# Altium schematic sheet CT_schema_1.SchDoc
size 464 x 450 mm
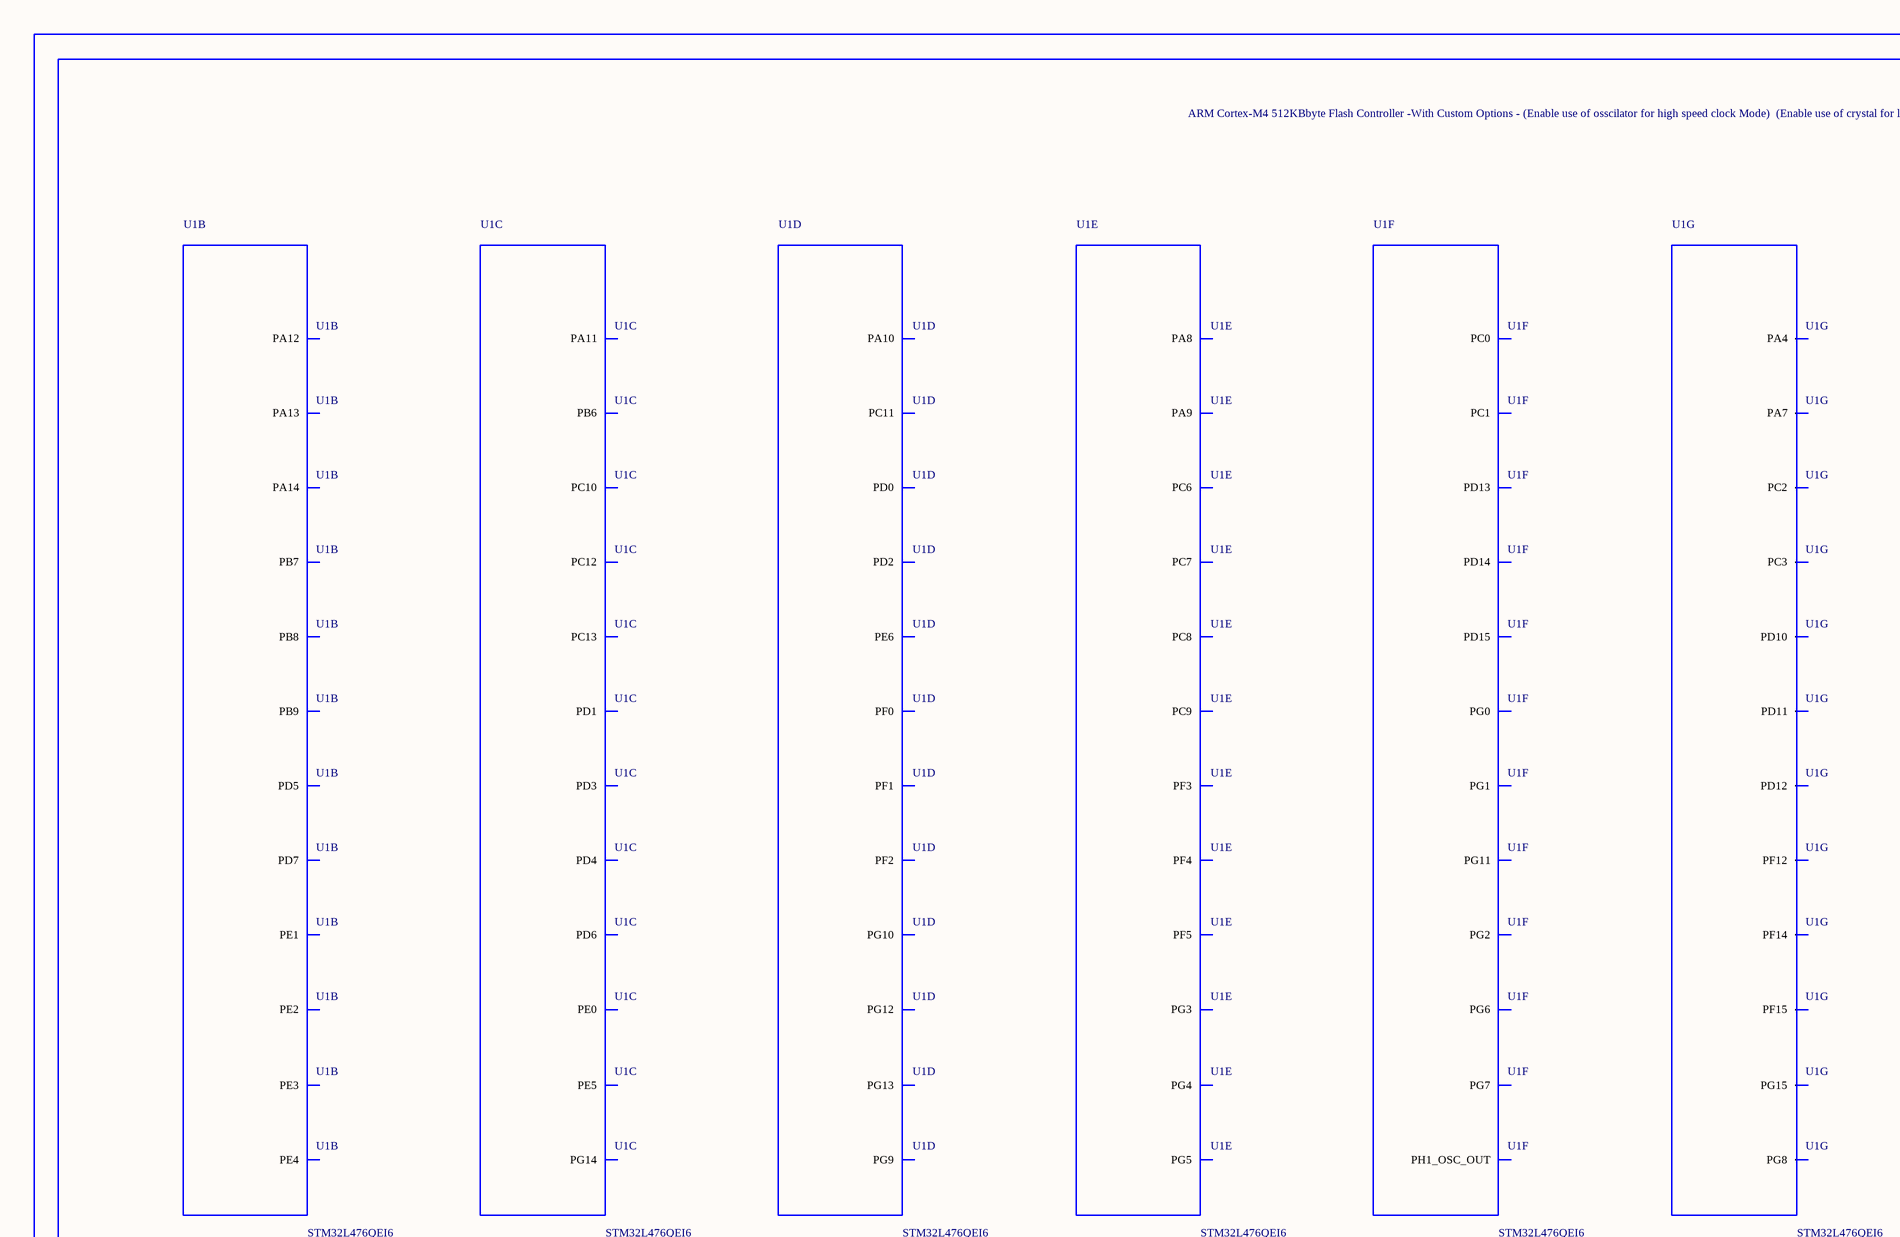
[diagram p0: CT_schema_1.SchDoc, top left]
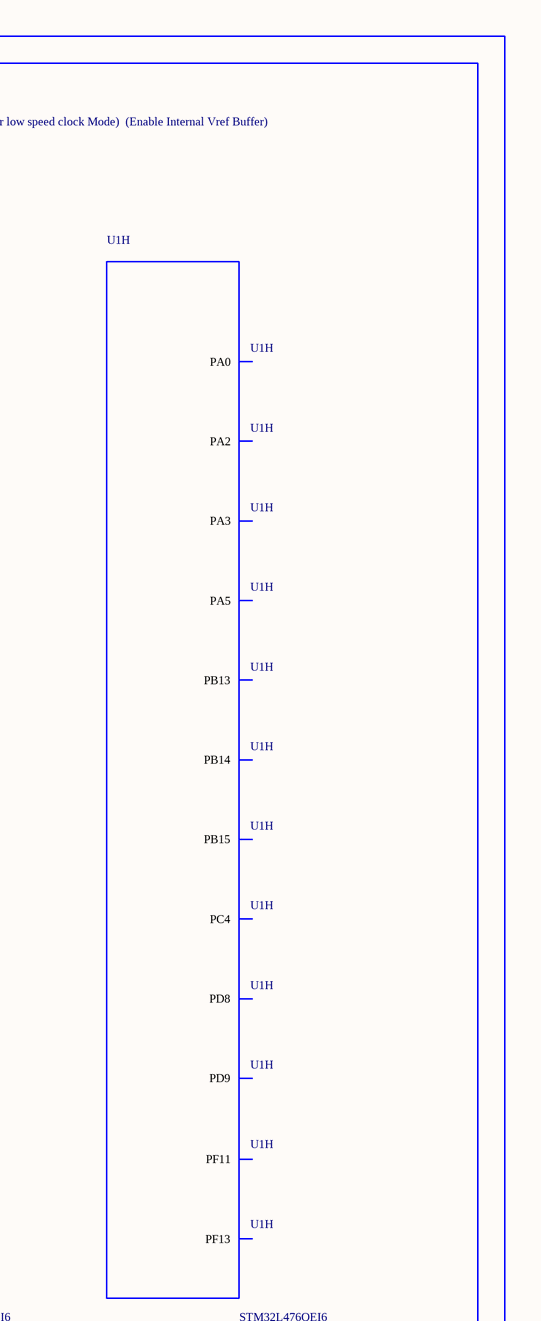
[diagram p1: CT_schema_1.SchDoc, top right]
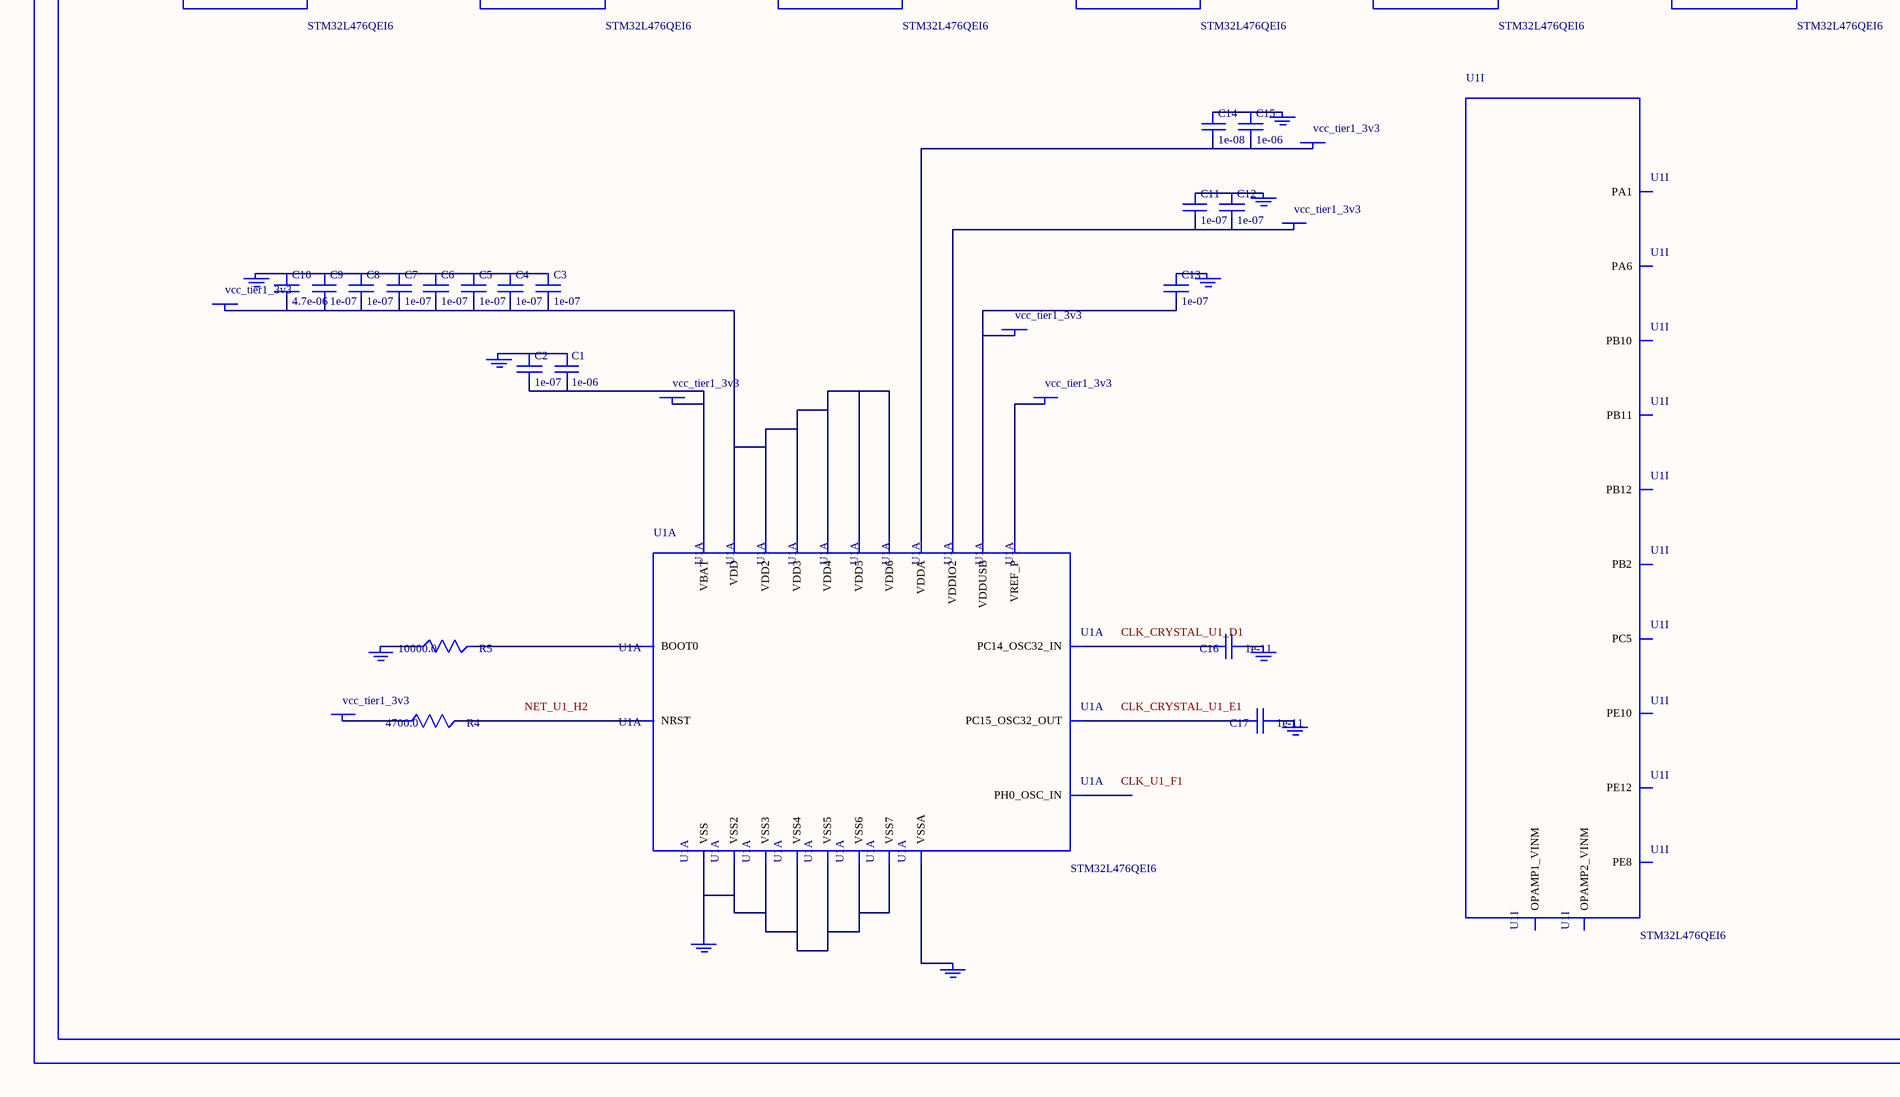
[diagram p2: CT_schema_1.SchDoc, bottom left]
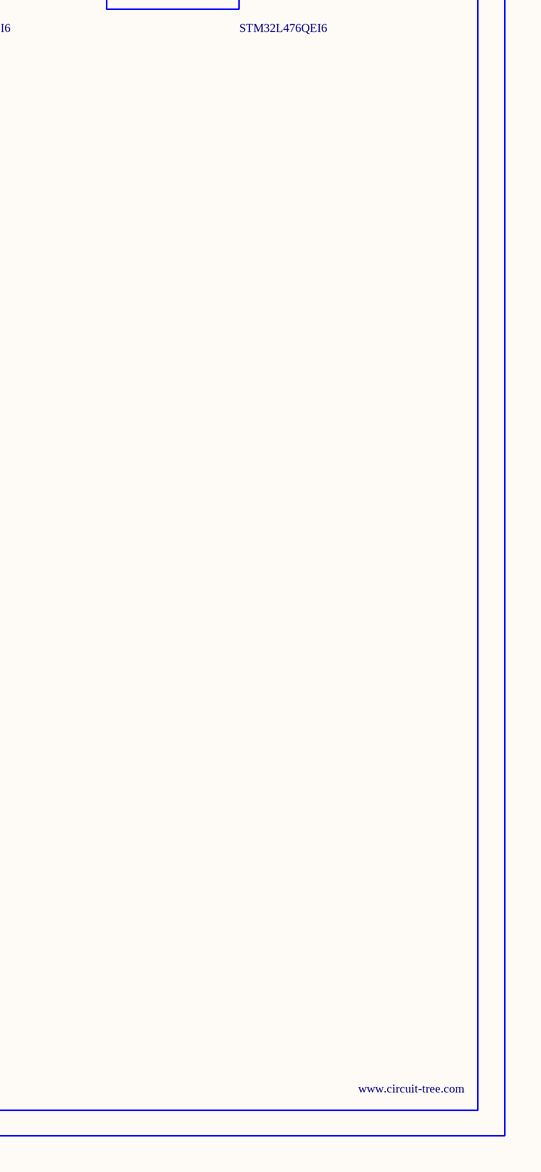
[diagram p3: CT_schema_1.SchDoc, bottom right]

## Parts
BORDER0  (no value)
C1  1e-06  [C0603]
C2  1e-07  [C0603]
C3  1e-07  [C0603]
C4  1e-07  [C0603]
C5  1e-07  [C0603]
C6  1e-07  [C0603]
C7  1e-07  [C0603]
C8  1e-07  [C0603]
C9  1e-07  [C0603]
C10  4.7e-06  [C0603]
C11  1e-07  [C0603]
C12  1e-07  [C0603]
C13  1e-07  [C0603]
C14  1e-08  [C0603]
C15  1e-06  [C0603]
C16  1e-11  [C0402]
C17  1e-11  [C0402]
GND_INSTANCE_0_0  (no value)
GND_INSTANCE_0_1  (no value)
GND_INSTANCE_0_2  (no value)
GND_INSTANCE_0_3  (no value)
GND_INSTANCE_0_4  (no value)
GND_INSTANCE_0_5  (no value)
GND_INSTANCE_0_6  (no value)
GND_INSTANCE_0_7  (no value)
GND_INSTANCE_0_8  (no value)
GND_INSTANCE_0_9  (no value)
POWER_INSTANCE_0_0  vcc_tier1_3v3
POWER_INSTANCE_0_1  vcc_tier1_3v3
POWER_INSTANCE_0_2  vcc_tier1_3v3
POWER_INSTANCE_0_3  vcc_tier1_3v3
POWER_INSTANCE_0_4  vcc_tier1_3v3
POWER_INSTANCE_0_5  vcc_tier1_3v3
POWER_INSTANCE_0_6  vcc_tier1_3v3
R4  4700.0  [R0603]
R5  10000.0  [R0603]
U1  STM32L476QEI6  [UFBGA132]  (parts A,B,C,D,E,F,G,H,I of 10)

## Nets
NetC1_1: C1.1 C2.1 GND_INSTANCE_0_0.0(GND)
NetC1_2: C1.2 C2.2 POWER_INSTANCE_0_0.0(PWR) U1.E2(VBAT)
NetC3_1: C3.1 C4.1 C5.1 C6.1 C7.1 C8.1 C9.1 C10.1 GND_INSTANCE_0_1.0(GND)
NetC3_2: C3.2 C4.2 C5.2 C6.2 C7.2 C8.2 C9.2 C10.2 POWER_INSTANCE_0_1.0(PWR) U1.C4(VDD) U1.G2(VDD4) U1.G6(VDD5) U1.G11(VDD2) U1.G12(VDD3) U1.H3(VDD6)
NetC11_1: C11.1 C12.1 GND_INSTANCE_0_2.0(GND)
NetC11_2: C11.2 C12.2 POWER_INSTANCE_0_2.0(PWR) U1.G7(VDDIO2)
NetC13_1: C13.1 GND_INSTANCE_0_4.0(GND)
NetC13_2: C13.2 POWER_INSTANCE_0_3.0(PWR) U1.C11(VDDUSB)
NetC14_1: C14.1 C15.1 GND_INSTANCE_0_5.0(GND)
NetC14_2: C14.2 C15.2 POWER_INSTANCE_0_4.0(PWR) U1.M1(VDDA)
NetC16_1: C16.1 GND_INSTANCE_0_6.0(GND)
NetC16_2: C16.2 U1.D1(PC14_OSC32_IN)
NetC17_1: C17.1 GND_INSTANCE_0_7.0(GND)
NetC17_2: C17.2 U1.E1(PC15_OSC32_OUT)
NetGND_INSTANCE_0_3_0: GND_INSTANCE_0_3.0(GND) R5.1
NetGND_INSTANCE_0_8_0: GND_INSTANCE_0_8.0(GND) U1.J1(VSSA)
NetGND_INSTANCE_0_9_0: GND_INSTANCE_0_9.0(GND) U1.D3(VSS) U1.E3(VSS2) U1.F2(VSS5) U1.F6(VSS6) U1.F7(VSS7) U1.F11(VSS3) U1.F12(VSS4)
NetPOWER_INSTANCE_0_5_0: POWER_INSTANCE_0_5.0(PWR) U1.L1(VREF_P)
NetPOWER_INSTANCE_0_6_0: POWER_INSTANCE_0_6.0(PWR) R4.1
NetR4_2: R4.2 U1.H2(NRST)
NetR5_2: R5.2 U1.A4(BOOT0)

Not connected (* = marked no-connect by the designer): U1 A1(PE3) A2(PE1) A3(PB8) A5(PD7) A6(PD5) A10(PA14) A11(PA13) A12(PA12) B1(PE4) B2(PE2) B3(PB9) B4(PB7) B5(PB6) B6(PD6) B7(PD4) B8(PD3) B9(PD1) B10(PC12) B11(PC10) B12(PA11) C1(PC13) C2(PE5) C3(PE0) C6(PG14) C7(PG13) C8(PD2) C9(PD0) C10(PC11) C12(PA10) D2(PE6) D4(PF2) D5(PF1) D6(PF0) D7(PG12) D8(PG10) D9(PG9) D10(PA9) D11(PA8) D12(PC9) E4(PF3) E9(PG5) E10(PC8) E11(PC7) E12(PC6) F1(PH0_OSC_IN) F3(PF4) F4(PF5) F9(PG3) F10(PG4) G1(PH1_OSC_OUT) G3(PG11) G4(PG6) G9(PG1) G10(PG2) H1(PC0) H4(PG7) H9(PG0) H10(PD15) H11(PD14) H12(PD13) J2(PC1) J3(PC2) J4(PA4) J5(PA7) J6(PG8) J7(PF12) J8(PF14) J9(PF15) J10(PD12) J11(PD11) J12(PD10) K1(PG15) K2(PC3) K3(PA2) K4(PA5) K5(PC4) K6(PF11) K7(PF13) K8(PD9) K9(PD8) K10(PB15) K11(PB14) K12(PB13) L2(PA0) L3(PA3) L4(PA6) L5(PC5) L6(PB2) L7(PE8) L8(PE10) L9(PE12) L10(PB10) L11(PB11) L12(PB12) M2(PA1) M3(OPAMP1_VINM) M4(OPAMP2_VINM)

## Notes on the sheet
- Labels drawn without touching a wire or pin: CLK_CRYSTAL_U1_D1, CLK_CRYSTAL_U1_E1, CLK_U1_F1, NET_U1_H2

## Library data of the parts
BORDER0 = BORDER_PAGE0
C1 C15 = C0603C105K3RACTU
C2-C9 C11-C13 = 06035C104K4Z2A
C10 = GRM188R6YA475KE15D
C14 = 06035C103K4Z2A
C16 C17 = C0402C100K3GACTU
GND_INSTANCE_0_0-GND_INSTANCE_0_9 = GND
POWER_INSTANCE_0_0-POWER_INSTANCE_0_6 = PWR
R4 = RC0603JR-074K7L
R5 = RC0603JR-0710KL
